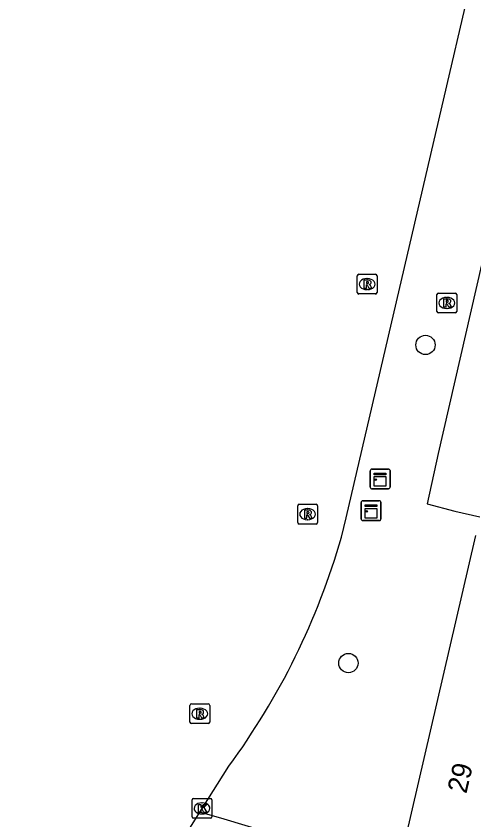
# Model space of a CAD drawing. Extents: x 161801 to 162379, y 382315 to 382832.
# Drawn here: x 161831.16 to 161854.33, y 382596.59 to 382637.32 of the extents above; entities that cross this region are included whole.
import ezdxf

# ---------------------------------------------------------------- set-up
doc = ezdxf.new("R2010")
doc.units = 0
for name, color, linetype in [('IMGEO_Boom', 7, 'Continuous'), ('IMGEO_Kast', 7, 'Continuous'), ('IMGEO_Kolk', 7, 'Continuous'), ('IMGEO_Pand', 7, 'Continuous'), ('IMGEO_Pand_nummerreeks', 7, 'Continuous'), ('IMGEO_Rijbaan_lokaal_gesloten', 7, 'Continuous'), ('IMGEO_Rioolput', 7, 'Continuous'), ('IMGEO_Voetpad_open', 7, 'Continuous')]:
    doc.layers.add(name, color=color, linetype=linetype)

msp = doc.modelspace()

# ---------------------------------------------------------------- linework, layer by layer
at = {"layer": 'IMGEO_Boom'}
for centre in [(161851.88, 382620.655), (161847.979, 382604.538)]:
    msp.add_circle(centre, 0.489, dxfattribs=at)
at = {"layer": 'IMGEO_Kast'}
for p, q in [((161849.086, 382613.443), (161849.086, 382614.284)), ((161849.086, 382614.284), (161849.086, 382613.443)), ((161849.161, 382614.368), (161850.002, 382614.368)), ((161850.002, 382614.368), (161849.161, 382614.368)), ((161850.086, 382614.293), (161850.086, 382613.452)), ((161850.086, 382613.452), (161850.086, 382614.293)), ((161850.011, 382613.368), (161849.17, 382613.368)), ((161849.17, 382613.368), (161850.011, 382613.368)), ((161848.626, 382611.833), (161848.626, 382612.674)), ((161848.626, 382612.674), (161848.626, 382611.833)), ((161848.701, 382612.758), (161849.542, 382612.758)), ((161849.542, 382612.758), (161848.701, 382612.758)), ((161849.626, 382612.683), (161849.626, 382611.842)), ((161849.626, 382611.842), (161849.626, 382612.683)), ((161849.551, 382611.758), (161848.71, 382611.758)), ((161848.71, 382611.758), (161849.551, 382611.758))]:
    msp.add_line(p, q, dxfattribs=at)
for points in [[(161849.281, 382614.158), (161849.881, 382614.158), (161849.881, 382614.073), (161849.281, 382614.073), (161849.281, 382614.158)], [(161849.281, 382613.983), (161849.881, 382613.983), (161849.881, 382613.494), (161849.281, 382613.494), (161849.281, 382613.983)], [(161848.821, 382612.548), (161849.421, 382612.548), (161849.421, 382612.463), (161848.821, 382612.463), (161848.821, 382612.548)], [(161848.821, 382612.373), (161849.421, 382612.373), (161849.421, 382611.884), (161848.821, 382611.884), (161848.821, 382612.373)]]:
    msp.add_lwpolyline(points, dxfattribs=at)
for centre in [(161849.365, 382613.832), (161848.905, 382612.222)]:
    msp.add_circle(centre, 0.0377, dxfattribs=at)
for centre, start, end in [((161849.164, 382614.29), 92.4484, 184.2845), ((161849.164, 382614.29), 92.4484, 184.2845), ((161850.008, 382614.29), 2.4484, 94.2845), ((161850.008, 382614.29), 2.4484, 94.2845), ((161849.164, 382613.446), 182.4484, 274.2845), ((161849.164, 382613.446), 182.4484, 274.2845), ((161850.008, 382613.446), 272.4484, 4.2845), ((161850.008, 382613.446), 272.4484, 4.2845), ((161848.704, 382612.68), 92.4484, 184.2845), ((161848.704, 382612.68), 92.4484, 184.2845), ((161849.548, 382612.68), 2.4484, 94.2845), ((161849.548, 382612.68), 2.4484, 94.2845), ((161848.704, 382611.836), 182.4484, 274.2845), ((161848.704, 382611.836), 182.4484, 274.2845), ((161849.548, 382611.836), 272.4484, 4.2845), ((161849.548, 382611.836), 272.4484, 4.2845)]:
    msp.add_arc(centre, 0.0779, start, end, dxfattribs=at)
at = {"layer": 'IMGEO_Kolk'}
for p, q in [((161840.066, 382596.749), (161840.066, 382597.601)), ((161840.141, 382597.675), (161840.993, 382597.675)), ((161841.067, 382597.601), (161841.067, 382596.749)), ((161840.554, 382597.455), (161840.579, 382597.455)), ((161840.577, 382596.895), (161840.552, 382596.895)), ((161840.993, 382596.675), (161840.141, 382596.675))]:
    msp.add_line(p, q, dxfattribs=at)
for points in [[(161840.066, 382596.749), (161840.066, 382597.601)], [(161840.141, 382597.675), (161840.993, 382597.675)], [(161841.067, 382597.601), (161841.067, 382596.749)], [(161840.387, 382597.375), (161840.51, 382597.375), (161840.51, 382597.224), (161840.64, 382597.375), (161840.804, 382597.375), (161840.658, 382597.224), (161840.811, 382596.975), (161840.659, 382596.975), (161840.574, 382597.139), (161840.51, 382597.072), (161840.51, 382596.975), (161840.387, 382596.975), (161840.387, 382597.375)], [(161840.993, 382596.675), (161840.141, 382596.675)]]:
    msp.add_lwpolyline(points, dxfattribs=at)
for centre, start, end in [((161840.143, 382597.599), 91.552, 178.448), ((161840.143, 382597.599), 91.552, 178.448), ((161840.991, 382597.599), 1.552, 88.448), ((161840.991, 382597.599), 1.552, 88.448), ((161840.143, 382596.751), 181.552, 268.448), ((161840.143, 382596.751), 181.552, 268.448), ((161840.991, 382596.751), 271.552, 358.448), ((161840.991, 382596.751), 271.552, 358.448)]:
    msp.add_arc(centre, 0.0765, start, end, dxfattribs=at)
for centre, major_axis, ratio, start_param, end_param in [((161840.553, 382597.175), (-0.387, 0.002), 0.722429, 4.712389, 7.853982), ((161840.578, 382597.175), (-0.39, 0.002), 0.717154, 1.570796, 4.712389)]:
    msp.add_ellipse(centre, major_axis=major_axis, ratio=ratio, start_param=start_param, end_param=end_param, dxfattribs=at)
at = {"layer": 'IMGEO_Pand'}
msp.add_lwpolyline([(161854.417, 382610.994), (161848.273, 382584.466)], dxfattribs=at)
at = {"layer": 'IMGEO_Rijbaan_lokaal_gesloten'}
for points in [[(161847.621, 382610.917), (161847.865, 382611.889), (161858.977, 382659.682)], [(161840.454, 382596.992), (161840.567, 382597.175), (161841.918, 382599.307)], [(161839.132, 382594.84), (161840.454, 382596.992)]]:
    msp.add_lwpolyline(points, dxfattribs=at)
msp.add_arc((161812.716, 382620.857), 36.292, 323.5737, 344.1044, dxfattribs=at)
at = {"layer": 'IMGEO_Rioolput'}
for p, q in [((161848.429, 382623.311), (161848.429, 382624.163)), ((161848.504, 382624.237), (161849.356, 382624.237)), ((161848.917, 382624.017), (161848.942, 382624.017)), ((161849.43, 382624.163), (161849.43, 382623.311)), ((161849.356, 382623.237), (161848.504, 382623.237)), ((161848.94, 382623.457), (161848.915, 382623.457)), ((161852.462, 382622.357), (161852.462, 382623.209)), ((161852.537, 382623.283), (161853.389, 382623.283)), ((161853.463, 382623.209), (161853.463, 382622.357)), ((161852.95, 382623.063), (161852.975, 382623.063)), ((161852.973, 382622.503), (161852.948, 382622.503)), ((161853.389, 382622.283), (161852.537, 382622.283)), ((161845.487, 382612.582), (161846.339, 382612.582)), ((161845.412, 382611.656), (161845.412, 382612.508)), ((161845.9, 382612.362), (161845.925, 382612.362)), ((161846.413, 382612.508), (161846.413, 382611.656)), ((161845.923, 382611.802), (161845.898, 382611.802)), ((161846.339, 382611.582), (161845.487, 382611.582)), ((161839.954, 382601.543), (161839.954, 382602.395)), ((161840.029, 382602.469), (161840.881, 382602.469)), ((161840.955, 382602.395), (161840.955, 382601.543)), ((161840.442, 382602.249), (161840.467, 382602.249)), ((161840.465, 382601.689), (161840.44, 382601.689)), ((161840.881, 382601.469), (161840.029, 382601.469))]:
    msp.add_line(p, q, dxfattribs=at)
for points in [[(161848.429, 382623.311), (161848.429, 382624.163)], [(161848.504, 382624.237), (161849.356, 382624.237)], [(161849.43, 382624.163), (161849.43, 382623.311)], [(161849.018, 382623.935), (161848.766, 382623.937), (161848.766, 382623.537)], [(161848.766, 382623.537), (161848.89, 382623.537), (161848.89, 382623.699), (161848.901, 382623.699)], [(161848.944, 382623.856), (161848.89, 382623.856), (161848.89, 382623.775)], [(161848.89, 382623.775), (161848.942, 382623.775)], [(161848.948, 382623.67), (161849.019, 382623.537), (161849.159, 382623.537), (161849.094, 382623.663)], [(161849.356, 382623.237), (161848.504, 382623.237)], [(161852.462, 382622.357), (161852.462, 382623.209)], [(161852.537, 382623.283), (161853.389, 382623.283)], [(161853.463, 382623.209), (161853.463, 382622.357)], [(161853.051, 382622.981), (161852.799, 382622.983), (161852.799, 382622.583)], [(161852.799, 382622.583), (161852.923, 382622.583), (161852.923, 382622.745), (161852.934, 382622.745)], [(161852.977, 382622.902), (161852.923, 382622.902), (161852.923, 382622.821)], [(161852.923, 382622.821), (161852.975, 382622.821)], [(161852.981, 382622.716), (161853.052, 382622.583), (161853.192, 382622.583), (161853.127, 382622.709)], [(161853.389, 382622.283), (161852.537, 382622.283)], [(161845.487, 382612.582), (161846.339, 382612.582)], [(161845.412, 382611.656), (161845.412, 382612.508)], [(161846.001, 382612.28), (161845.749, 382612.282), (161845.749, 382611.882)], [(161845.927, 382612.201), (161845.873, 382612.201), (161845.873, 382612.12)], [(161846.413, 382612.508), (161846.413, 382611.656)], [(161845.749, 382611.882), (161845.873, 382611.882), (161845.873, 382612.044), (161845.884, 382612.044)], [(161845.873, 382612.12), (161845.925, 382612.12)], [(161845.931, 382612.015), (161846.002, 382611.882), (161846.142, 382611.882), (161846.077, 382612.008)], [(161846.339, 382611.582), (161845.487, 382611.582)], [(161839.954, 382601.543), (161839.954, 382602.395)], [(161840.029, 382602.469), (161840.881, 382602.469)], [(161840.955, 382602.395), (161840.955, 382601.543)], [(161840.543, 382602.167), (161840.291, 382602.169), (161840.291, 382601.769)], [(161840.469, 382602.088), (161840.415, 382602.088), (161840.415, 382602.007)], [(161840.415, 382602.007), (161840.467, 382602.007)], [(161840.291, 382601.769), (161840.415, 382601.769), (161840.415, 382601.931), (161840.426, 382601.931)], [(161840.473, 382601.902), (161840.544, 382601.769), (161840.684, 382601.769), (161840.619, 382601.895)], [(161840.881, 382601.469), (161840.029, 382601.469)]]:
    msp.add_lwpolyline(points, dxfattribs=at)
for centre, radius, start, end in [((161848.506, 382624.161), 0.0765, 91.552, 178.448), ((161848.506, 382624.161), 0.0765, 91.552, 178.448), ((161849.354, 382624.161), 0.0765, 1.552, 88.448), ((161849.354, 382624.161), 0.0765, 1.552, 88.448), ((161848.9, 382623.646), 0.0533, 26.0293, 88.6989), ((161848.926, 382623.964), 0.19, 274.7715, 282.9687), ((161848.95, 382623.76), 0.0964, 77.0061, 93.1865), ((161848.964, 382623.817), 0.0378, 276.6634, 79.6772), ((161849.017, 382623.825), 0.109, 350.3612, 89.416), ((161849.015, 382623.825), 0.112, 277.5842, 350.9817), ((161848.999, 382623.61), 0.108, 29.5134, 73.7905), ((161848.506, 382623.313), 0.0765, 181.552, 268.448), ((161848.506, 382623.313), 0.0765, 181.552, 268.448), ((161849.354, 382623.313), 0.0765, 271.552, 358.448), ((161849.354, 382623.313), 0.0765, 271.552, 358.448), ((161852.539, 382623.207), 0.0765, 91.552, 178.448), ((161852.539, 382623.207), 0.0765, 91.552, 178.448), ((161853.387, 382623.207), 0.0765, 1.552, 88.448), ((161853.387, 382623.207), 0.0765, 1.552, 88.448), ((161852.933, 382622.692), 0.0533, 26.0293, 88.6989), ((161852.959, 382623.01), 0.19, 274.7715, 282.9687), ((161852.983, 382622.806), 0.0964, 77.0061, 93.1865), ((161852.997, 382622.863), 0.0378, 276.6634, 79.6772), ((161853.05, 382622.871), 0.109, 350.3612, 89.416), ((161853.048, 382622.871), 0.112, 277.5842, 350.9817), ((161853.032, 382622.656), 0.108, 29.5134, 73.7905), ((161852.539, 382622.359), 0.0765, 181.552, 268.448), ((161852.539, 382622.359), 0.0765, 181.552, 268.448), ((161853.387, 382622.359), 0.0765, 271.552, 358.448), ((161853.387, 382622.359), 0.0765, 271.552, 358.448), ((161845.489, 382612.506), 0.0765, 91.552, 178.448), ((161845.489, 382612.506), 0.0765, 91.552, 178.448), ((161846.337, 382612.506), 0.0765, 1.552, 88.448), ((161846.337, 382612.506), 0.0765, 1.552, 88.448), ((161845.933, 382612.105), 0.0964, 77.0061, 93.1865), ((161845.947, 382612.162), 0.0378, 276.6634, 79.6772), ((161846, 382612.17), 0.109, 350.3612, 89.416), ((161845.883, 382611.991), 0.0533, 26.0293, 88.6989), ((161845.909, 382612.309), 0.19, 274.7715, 282.9687), ((161845.998, 382612.17), 0.112, 277.5842, 350.9817), ((161845.982, 382611.955), 0.108, 29.5134, 73.7905), ((161845.489, 382611.658), 0.0765, 181.552, 268.448), ((161845.489, 382611.658), 0.0765, 181.552, 268.448), ((161846.337, 382611.658), 0.0765, 271.552, 358.448), ((161846.337, 382611.658), 0.0765, 271.552, 358.448), ((161840.031, 382602.393), 0.0765, 91.552, 178.448), ((161840.031, 382602.393), 0.0765, 91.552, 178.448), ((161840.879, 382602.393), 0.0765, 1.552, 88.448), ((161840.879, 382602.393), 0.0765, 1.552, 88.448), ((161840.451, 382602.196), 0.19, 274.7715, 282.9687), ((161840.475, 382601.992), 0.0964, 77.0061, 93.1865), ((161840.489, 382602.049), 0.0378, 276.6634, 79.6772), ((161840.542, 382602.057), 0.109, 350.3612, 89.416), ((161840.54, 382602.057), 0.112, 277.5842, 350.9817), ((161840.425, 382601.878), 0.0533, 26.0293, 88.6989), ((161840.524, 382601.842), 0.108, 29.5134, 73.7905), ((161840.031, 382601.545), 0.0765, 181.552, 268.448), ((161840.031, 382601.545), 0.0765, 181.552, 268.448), ((161840.879, 382601.545), 0.0765, 271.552, 358.448), ((161840.879, 382601.545), 0.0765, 271.552, 358.448)]:
    msp.add_arc(centre, radius, start, end, dxfattribs=at)
for centre, major_axis, ratio, start_param, end_param in [((161848.916, 382623.737), (-0.387, 0.002), 0.722429, 4.712389, 7.853982), ((161848.941, 382623.737), (-0.39, 0.002), 0.717154, 1.570796, 4.712389), ((161852.949, 382622.783), (-0.387, 0.002), 0.722429, 4.712389, 7.853982), ((161852.974, 382622.783), (-0.39, 0.002), 0.717154, 1.570796, 4.712389), ((161845.899, 382612.082), (-0.387, 0.002), 0.722429, 4.712389, 7.853982), ((161845.924, 382612.082), (-0.39, 0.002), 0.717154, 1.570796, 4.712389), ((161840.441, 382601.969), (-0.387, 0.002), 0.722429, 4.712389, 7.853982), ((161840.466, 382601.969), (-0.39, 0.002), 0.717154, 1.570796, 4.712389)]:
    msp.add_ellipse(centre, major_axis=major_axis, ratio=ratio, start_param=start_param, end_param=end_param, dxfattribs=at)
at = {"layer": 'IMGEO_Voetpad_open'}
for points in [[(161862.499, 382658.624), (161852.515, 382615.16), (161851.961, 382612.607), (161853.365, 382612.238), (161854.625, 382611.948)], [(161831.156, 382568.929), (161831.218, 382568.893), (161843.807, 382595.992), (161841.688, 382596.624), (161840.454, 382596.992)]]:
    msp.add_lwpolyline(points, dxfattribs=at)

# ---------------------------------------------------------------- texts
at = {"layer": 'IMGEO_Pand_nummerreeks'}
msp.add_text('29', height=1, rotation=76.7592, dxfattribs=at).set_placement((161853.945, 382597.886))

doc.saveas('drawing.dxf')
